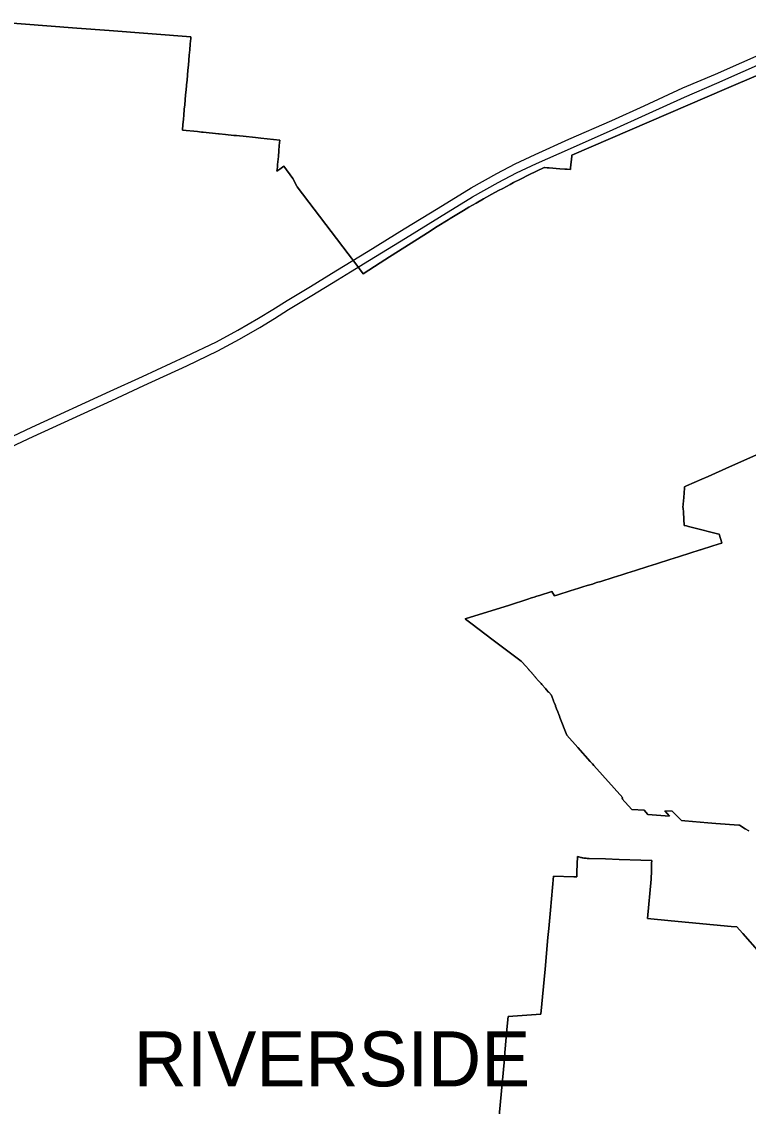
# Model space of a CAD drawing. Extents: x 0 to 34, y 0 to 22.
# Drawn here: x 5.4783 to 5.5845, y 15.203 to 15.3615 of the extents above; entities that cross this region are included whole.
import ezdxf

# ---------------------------------------------------------------- set-up
doc = ezdxf.new("R2010")
doc.units = 0
for name, color, linetype in [('GM_X_Corporation', 7, 'Continuous'), ('GM_X_Corporation_Text', 7, 'Continuous'), ('GM_X_State_Route', 7, 'Continuous')]:
    doc.layers.add(name, color=color, linetype=linetype)

msp = doc.modelspace()

# ---------------------------------------------------------------- linework, layer by layer
at = {"layer": 'GM_X_Corporation'}
for points in [[(5.58601, 15.35379), (5.58132, 15.35177), (5.55874, 15.34204), (5.55872, 15.3419), (5.55855, 15.34017), (5.55852, 15.33993), (5.55804, 15.33996), (5.55768, 15.33999), (5.55696, 15.34004), (5.55543, 15.34016), (5.55512, 15.34018), (5.55474, 15.34021), (5.5547, 15.34021), (5.55245, 15.33913), (5.55124, 15.33852), (5.55022, 15.33801), (5.54971, 15.33773), (5.54862, 15.33716), (5.54801, 15.33684), (5.54705, 15.33631), (5.54583, 15.33564), (5.54475, 15.33503), (5.54366, 15.3344), (5.54287, 15.33393), (5.54095, 15.33278), (5.54064, 15.33259), (5.53906, 15.33158), (5.53761, 15.33066), (5.53619, 15.32975), (5.53209, 15.32715), (5.53072, 15.32628), (5.52822, 15.32469), (5.52714, 15.32616), (5.52606, 15.32762), (5.51859, 15.33741), (5.51854, 15.33747), (5.51853, 15.3375), (5.51797, 15.33859), (5.51663, 15.3404), (5.51604, 15.33997), (5.51564, 15.33967), (5.5157, 15.34029), (5.51573, 15.34066), (5.51584, 15.34184), (5.51591, 15.34264), (5.51598, 15.34343), (5.51605, 15.34423), (5.51328, 15.34452), (5.51252, 15.34459), (5.51068, 15.34478), (5.51015, 15.34484), (5.50973, 15.34488), (5.50933, 15.34492), (5.50814, 15.34504), (5.50721, 15.34514), (5.50709, 15.34515), (5.50485, 15.34538), (5.50461, 15.34541), (5.50405, 15.34546), (5.50182, 15.34569), (5.50189, 15.34649), (5.50196, 15.34722), (5.50203, 15.34794), (5.50209, 15.34867), (5.5021, 15.34877), (5.50216, 15.34939), (5.50223, 15.35012), (5.50229, 15.35084), (5.50236, 15.35156), (5.50242, 15.35221), (5.50243, 15.35229), (5.5025, 15.35301), (5.50256, 15.35374), (5.50263, 15.35446), (5.5027, 15.35519), (5.50277, 15.35591), (5.50283, 15.35663), (5.50291, 15.35743), (5.50298, 15.35824), (5.50302, 15.35876), (5.50305, 15.35904), (5.50307, 15.35932), (5.49111, 15.36025), (5.4864, 15.36061), (5.47446, 15.36154)], [(5.47446, 15.36154), (5.4864, 15.36061), (5.49111, 15.36025), (5.50307, 15.35932), (5.50305, 15.35904), (5.50302, 15.35876), (5.50298, 15.35824), (5.50291, 15.35743), (5.50283, 15.35663), (5.50277, 15.35591), (5.5027, 15.35519), (5.50263, 15.35446), (5.50256, 15.35374), (5.5025, 15.35301), (5.50243, 15.35229), (5.50242, 15.35221), (5.50236, 15.35156), (5.50229, 15.35084), (5.50223, 15.35012), (5.50216, 15.34939), (5.5021, 15.34877), (5.50209, 15.34867), (5.50203, 15.34794), (5.50196, 15.34722), (5.50189, 15.34649), (5.50182, 15.34569), (5.50182, 15.34569), (5.50405, 15.34546), (5.50461, 15.34541), (5.50485, 15.34538), (5.50709, 15.34515), (5.50721, 15.34514), (5.50814, 15.34504), (5.50933, 15.34492), (5.50973, 15.34488), (5.51015, 15.34484), (5.51068, 15.34478), (5.51252, 15.34459), (5.51328, 15.34452), (5.51605, 15.34423), (5.51605, 15.34423), (5.51598, 15.34343), (5.51591, 15.34266), (5.51591, 15.34264), (5.51584, 15.34184), (5.51573, 15.34066), (5.5157, 15.34029), (5.51564, 15.33967), (5.51604, 15.33997), (5.51663, 15.3404), (5.51797, 15.33859), (5.51853, 15.3375), (5.51854, 15.33747), (5.51859, 15.33741), (5.52606, 15.32762), (5.52714, 15.32616), (5.52822, 15.32469), (5.53072, 15.32628), (5.53209, 15.32715), (5.53619, 15.32975), (5.53761, 15.33066), (5.53906, 15.33158), (5.54064, 15.33259), (5.54095, 15.33278), (5.54287, 15.33393), (5.54366, 15.3344), (5.54475, 15.33503), (5.54583, 15.33564), (5.54705, 15.33631), (5.54801, 15.33684), (5.54862, 15.33716), (5.54971, 15.33773), (5.55022, 15.33801), (5.55124, 15.33852), (5.55245, 15.33913), (5.5547, 15.34021), (5.55475, 15.34021), (5.55512, 15.34018), (5.55543, 15.34016), (5.55696, 15.34004), (5.55768, 15.33999), (5.55804, 15.33996), (5.55852, 15.33993), (5.55855, 15.34017), (5.55872, 15.3419), (5.55874, 15.34204), (5.58132, 15.35177), (5.58601, 15.35379)], [(5.5846, 15.24325), (5.58403, 15.24353), (5.58323, 15.24406), (5.58313, 15.24407), (5.57975, 15.24434), (5.5786, 15.24443), (5.57523, 15.2447), (5.57475, 15.24474), (5.57422, 15.24529), (5.5734, 15.24613), (5.57229, 15.24617), (5.57299, 15.24538), (5.56984, 15.24564), (5.56927, 15.24627), (5.56747, 15.24635), (5.56603, 15.24798), (5.56615, 15.24808), (5.56194, 15.2528), (5.56194, 15.25281), (5.56173, 15.25305), (5.56141, 15.2534), (5.55959, 15.25544), (5.55798, 15.25725), (5.55699, 15.25981), (5.5569, 15.26005), (5.55687, 15.26012), (5.55662, 15.26077), (5.55659, 15.26084), (5.55634, 15.26149), (5.55632, 15.26155), (5.55613, 15.26203), (5.55606, 15.26221), (5.55604, 15.26226), (5.55578, 15.26293), (5.55576, 15.26298), (5.55573, 15.26306), (5.55534, 15.26351), (5.55531, 15.26354), (5.55496, 15.26393), (5.55486, 15.26405), (5.55483, 15.26408), (5.55438, 15.26459), (5.55435, 15.26463), (5.55422, 15.26478), (5.5539, 15.26514), (5.55387, 15.26517), (5.55342, 15.26568), (5.55339, 15.26572), (5.55294, 15.26623), (5.55291, 15.26626), (5.55286, 15.26632), (5.55268, 15.26653), (5.55267, 15.26654), (5.55246, 15.26677), (5.55243, 15.26681), (5.55198, 15.26731), (5.55195, 15.26735), (5.55145, 15.26792), (5.55133, 15.26805), (5.55094, 15.26835), (5.55093, 15.26835), (5.55093, 15.26835), (5.55014, 15.26895), (5.54704, 15.27129), (5.54417, 15.27345), (5.54317, 15.27421), (5.54315, 15.27422), (5.5496, 15.27626), (5.5523, 15.27712), (5.55284, 15.27729), (5.55322, 15.27741), (5.55361, 15.27753), (5.55399, 15.27765), (5.5558, 15.27822), (5.5558, 15.27822), (5.55581, 15.27822), (5.5562, 15.2776), (5.55621, 15.27759), (5.55666, 15.27773), (5.55727, 15.27793), (5.55789, 15.27812), (5.5585, 15.27832), (5.55911, 15.27851), (5.55973, 15.2787), (5.56034, 15.2789), (5.56095, 15.27909), (5.56172, 15.27933), (5.56233, 15.27953), (5.56294, 15.27972), (5.56356, 15.27991), (5.56417, 15.28011), (5.56478, 15.2803), (5.5654, 15.28049), (5.56601, 15.28069), (5.56678, 15.28093), (5.56739, 15.28112), (5.568, 15.28132), (5.56862, 15.28151), (5.56923, 15.2817), (5.56984, 15.2819), (5.57045, 15.28209), (5.57107, 15.28229), (5.57183, 15.28253), (5.57245, 15.28272), (5.57306, 15.28292), (5.57367, 15.28311), (5.57429, 15.2833), (5.5749, 15.2835), (5.57551, 15.28369), (5.57613, 15.28389), (5.57657, 15.28403), (5.57687, 15.28412), (5.57689, 15.28413), (5.57748, 15.28432), (5.5775, 15.28432), (5.5781, 15.28451), (5.57812, 15.28452), (5.57872, 15.28471), (5.57873, 15.28471), (5.57934, 15.2849), (5.57934, 15.2849), (5.57996, 15.2851), (5.57996, 15.2851), (5.58057, 15.28529), (5.58057, 15.28529), (5.58065, 15.28531), (5.58065, 15.28532), (5.58064, 15.28535), (5.58064, 15.28535), (5.58044, 15.286), (5.58043, 15.286), (5.58023, 15.28663), (5.58023, 15.28664), (5.58023, 15.28664), (5.58021, 15.28664), (5.57635, 15.2876), (5.57579, 15.28774), (5.57548, 15.28782), (5.57515, 15.2879), (5.57502, 15.28977), (5.57497, 15.29046), (5.57496, 15.29051), (5.57509, 15.29197), (5.57517, 15.29334), (5.57518, 15.29356), (5.57548, 15.29369), (5.57772, 15.29466), (5.57864, 15.29506), (5.58177, 15.29646), (5.59077, 15.30046)], [(5.59077, 15.30046), (5.58177, 15.29646), (5.57864, 15.29506), (5.57772, 15.29466), (5.57548, 15.29369), (5.57518, 15.29356), (5.57517, 15.29334), (5.57509, 15.29197), (5.57496, 15.29051), (5.57497, 15.29046), (5.57502, 15.28977), (5.57515, 15.2879), (5.57548, 15.28782), (5.57579, 15.28774), (5.57634, 15.2876), (5.58021, 15.28664), (5.58023, 15.28664), (5.58023, 15.28664), (5.58023, 15.28663), (5.58043, 15.286), (5.58044, 15.286), (5.58064, 15.28535), (5.58064, 15.28535), (5.58065, 15.28532), (5.58065, 15.28531), (5.58057, 15.28529), (5.58057, 15.28529), (5.57996, 15.2851), (5.57996, 15.2851), (5.57934, 15.2849), (5.57934, 15.2849), (5.57873, 15.28471), (5.57872, 15.28471), (5.57812, 15.28452), (5.5781, 15.28451), (5.5775, 15.28432), (5.57748, 15.28432), (5.57689, 15.28413), (5.57687, 15.28412), (5.57657, 15.28403), (5.57613, 15.28389), (5.57551, 15.28369), (5.5749, 15.2835), (5.57429, 15.2833), (5.57367, 15.28311), (5.57306, 15.28292), (5.57245, 15.28272), (5.57183, 15.28253), (5.57107, 15.28229), (5.57045, 15.28209), (5.56984, 15.2819), (5.56923, 15.28171), (5.56862, 15.28151), (5.568, 15.28132), (5.56739, 15.28112), (5.56678, 15.28093), (5.56601, 15.28069), (5.5654, 15.28049), (5.56478, 15.2803), (5.56417, 15.28011), (5.56356, 15.27991), (5.56294, 15.27972), (5.56233, 15.27953), (5.56172, 15.27933), (5.56095, 15.27909), (5.56034, 15.2789), (5.55973, 15.2787), (5.55911, 15.27851), (5.5585, 15.27832), (5.55789, 15.27812), (5.55727, 15.27793), (5.55666, 15.27773), (5.55621, 15.27759), (5.5562, 15.2776), (5.55581, 15.27822), (5.5558, 15.27822), (5.5558, 15.27822), (5.55399, 15.27765), (5.55361, 15.27753), (5.55322, 15.27741), (5.55284, 15.27729), (5.5523, 15.27712), (5.5496, 15.27626), (5.54315, 15.27422), (5.54315, 15.27422), (5.54315, 15.27422), (5.54317, 15.27421), (5.54417, 15.27345), (5.54704, 15.27129), (5.55014, 15.26895), (5.55093, 15.26835), (5.55094, 15.26835), (5.55133, 15.26805), (5.55145, 15.26792), (5.55195, 15.26735), (5.55198, 15.26731), (5.55243, 15.26681), (5.55246, 15.26677), (5.55267, 15.26654), (5.55268, 15.26653), (5.55286, 15.26632), (5.55289, 15.26629), (5.55291, 15.26626), (5.55294, 15.26623), (5.55339, 15.26572), (5.55342, 15.26568), (5.55387, 15.26517), (5.5539, 15.26514), (5.55422, 15.26478), (5.55435, 15.26463), (5.55438, 15.26459), (5.55483, 15.26408), (5.55486, 15.26405), (5.55496, 15.26393), (5.55531, 15.26354), (5.55534, 15.26351), (5.55573, 15.26306), (5.55576, 15.26298), (5.55578, 15.26293), (5.55604, 15.26226), (5.55606, 15.26221), (5.55613, 15.26203), (5.55632, 15.26155), (5.55634, 15.26149), (5.55659, 15.26084), (5.55662, 15.26077), (5.55687, 15.26012), (5.5569, 15.26005), (5.55699, 15.25981), (5.55798, 15.25725), (5.55959, 15.25544), (5.56141, 15.2534), (5.56173, 15.25305), (5.56194, 15.25281), (5.56194, 15.2528), (5.56615, 15.24808), (5.56603, 15.24798), (5.56747, 15.24635), (5.56927, 15.24627), (5.56984, 15.24564), (5.57299, 15.24538), (5.57229, 15.24617), (5.5734, 15.24613), (5.57422, 15.24529), (5.57475, 15.24474), (5.57523, 15.2447), (5.5786, 15.24443), (5.57975, 15.24434), (5.58313, 15.24407), (5.58323, 15.24406), (5.58403, 15.24353), (5.5846, 15.24325)], [(5.548, 15.20057), (5.54882, 15.20937), (5.54895, 15.21083), (5.54929, 15.21467), (5.54929, 15.2147), (5.54942, 15.2161), (5.55421, 15.21645), (5.55481, 15.223), (5.55523, 15.22766), (5.55535, 15.22896), (5.5556, 15.23166), (5.55605, 15.23664), (5.55903, 15.23654), (5.55946, 15.23653), (5.55947, 15.23725), (5.55953, 15.23948), (5.55964, 15.23945), (5.55976, 15.23942), (5.55988, 15.23939), (5.55999, 15.23936), (5.56011, 15.23934), (5.56023, 15.23931), (5.56035, 15.23929), (5.56047, 15.23927), (5.56053, 15.23927), (5.56059, 15.23926), (5.56071, 15.23924), (5.56083, 15.23923), (5.56095, 15.23922), (5.56107, 15.23921), (5.56124, 15.23921), (5.56364, 15.23913), (5.56565, 15.23907), (5.57039, 15.23892), (5.57037, 15.23845), (5.57034, 15.23739), (5.5703, 15.23619), (5.56977, 15.23042), (5.57325, 15.2301), (5.58199, 15.22927), (5.58285, 15.22919), (5.58322, 15.22879), (5.58371, 15.22823), (5.58621, 15.22542)], [(5.58621, 15.22542), (5.58371, 15.22823), (5.58322, 15.22879), (5.58285, 15.22919), (5.58199, 15.22927), (5.57325, 15.2301), (5.56977, 15.23042), (5.5703, 15.23619), (5.57034, 15.23739), (5.57037, 15.23845), (5.57039, 15.23892), (5.57038, 15.23892), (5.56565, 15.23907), (5.56364, 15.23913), (5.56124, 15.23921), (5.56107, 15.23921), (5.56095, 15.23922), (5.56083, 15.23923), (5.56071, 15.23924), (5.56059, 15.23926), (5.56053, 15.23927), (5.56047, 15.23927), (5.56035, 15.23929), (5.56023, 15.23931), (5.56011, 15.23934), (5.55999, 15.23936), (5.55988, 15.23939), (5.55976, 15.23942), (5.55964, 15.23945), (5.55953, 15.23948), (5.55947, 15.23725), (5.55946, 15.23653), (5.55903, 15.23654), (5.55605, 15.23664), (5.5556, 15.23166), (5.55535, 15.22896), (5.55523, 15.22766), (5.55481, 15.223), (5.55421, 15.21645), (5.54942, 15.2161), (5.54929, 15.2147), (5.54929, 15.21467), (5.54895, 15.21083), (5.54882, 15.20937), (5.548, 15.20058)]]:
    msp.add_lwpolyline(points, dxfattribs=at)
at = {"layer": 'GM_X_State_Route'}
for points in [[(5.47321, 15.29916), (5.47983, 15.30224), (5.49129, 15.30751), (5.49598, 15.30966), (5.50226, 15.31257), (5.50679, 15.31474), (5.50994, 15.31643), (5.51292, 15.31817), (5.51505, 15.31947), (5.51713, 15.32078), (5.52052, 15.32283), (5.52425, 15.32511), (5.52896, 15.32799), (5.53423, 15.33124), (5.5392, 15.33428), (5.54402, 15.33724), (5.54776, 15.33934), (5.55044, 15.34076), (5.55336, 15.34211), (5.5583, 15.34435), (5.56457, 15.34711), (5.56929, 15.34926), (5.57496, 15.35185), (5.57969, 15.35388), (5.5874, 15.35727)], [(5.52637, 15.32495), (5.52916, 15.32666), (5.53444, 15.32991), (5.53941, 15.33295), (5.54423, 15.33591), (5.54797, 15.33801), (5.55065, 15.33943), (5.55357, 15.34079), (5.55851, 15.34302), (5.56478, 15.34578), (5.5695, 15.34793), (5.57516, 15.35052), (5.5799, 15.35255), (5.5876, 15.35594), (5.58996, 15.35703)], [(5.47342, 15.29783), (5.48003, 15.30091), (5.4915, 15.30618), (5.49619, 15.30833), (5.50247, 15.31124), (5.50699, 15.31341), (5.51015, 15.3151), (5.51312, 15.31684), (5.51526, 15.31814), (5.51734, 15.31945), (5.52073, 15.32151), (5.52446, 15.32378), (5.52637, 15.32495)]]:
    msp.add_lwpolyline(points, dxfattribs=at)

# ---------------------------------------------------------------- texts
at = {"layer": 'GM_X_Corporation_Text'}
msp.add_text('RIVERSIDE', height=0.008037, rotation=0, dxfattribs=at).set_placement((5.49471, 15.20589))

doc.saveas('drawing.dxf')
